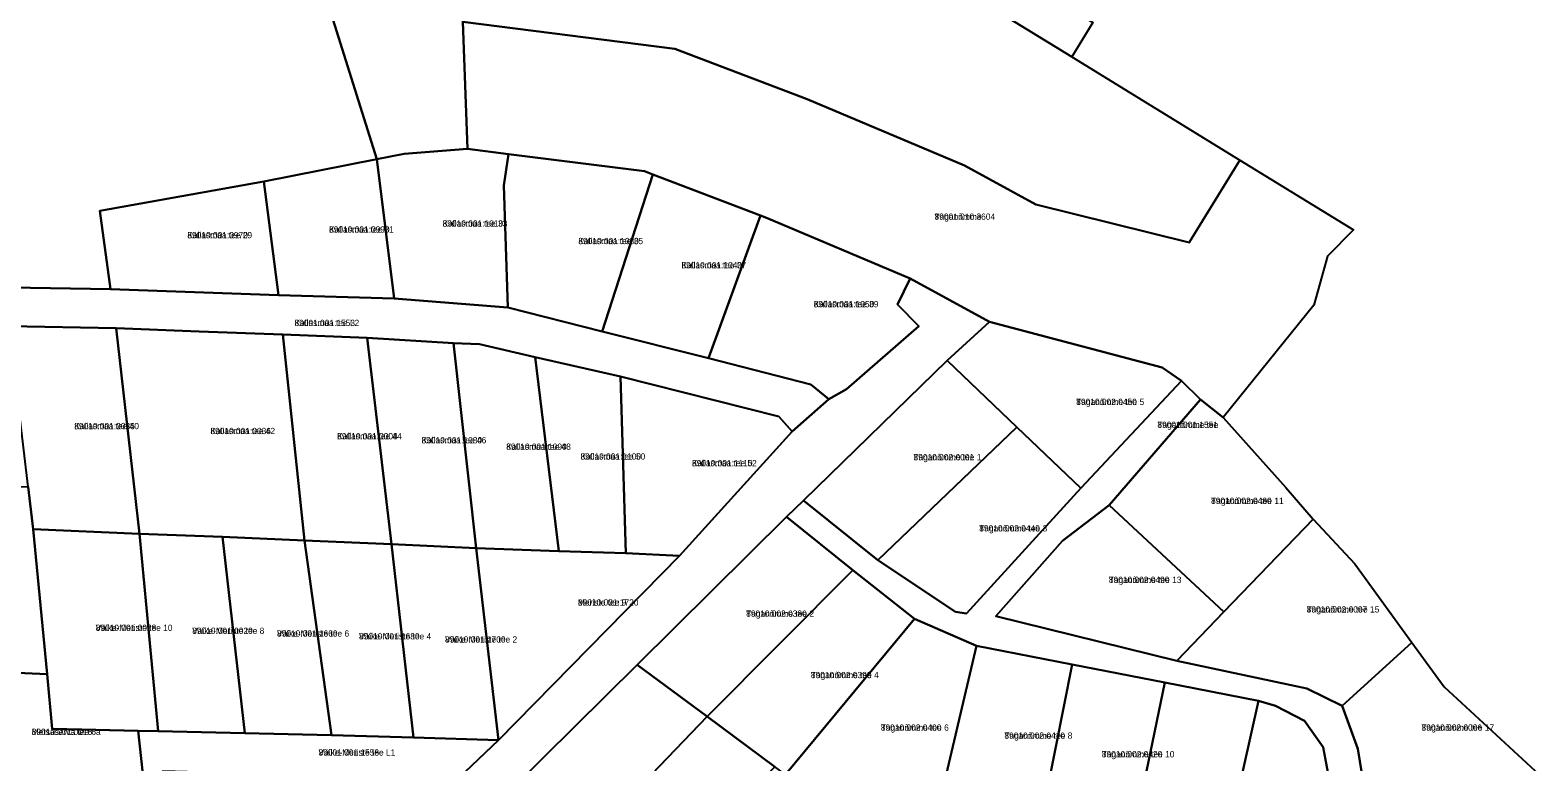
# Model space of a CAD drawing. Extents: x 526849 to 562296, y 6591741 to 6618546.
# Drawn here: x 554310.3 to 554671.4, y 6594193.2 to 6594368.5 of the extents above; entities that cross this region are included whole.
import ezdxf

# ---------------------------------------------------------------- set-up
doc = ezdxf.new("R2010")
doc.units = 0
for name, color, linetype in [('L_AADRESS', 7, 'Continuous'), ('PIIR', 7, 'Continuous'), ('TUNNUS', 7, 'Continuous')]:
    doc.layers.add(name, color=color, linetype=linetype)

msp = doc.modelspace()

# ---------------------------------------------------------------- linework, layer by layer
at = {"layer": 'PIIR'}
for points in [[(554049.07, 6594588.34), (554187.3, 6594577.01), (554142.16, 6594463.53), (554286.81, 6594430.65), (554294.86, 6594427.18), (554295.56, 6594417.13), (554326.06, 6594416.22), (554335.74, 6594428.53), (554338.1, 6594444.44), (554360.54, 6594442.08), (554393.31, 6594337.56), (554366.29, 6594332.23), (554326.99, 6594325.2), (554329.5, 6594306.39), (554305.59, 6594306.85), (554225.23, 6594322.81), (554036.66, 6594366.61)], [(554305.59, 6594306.85), (554329.5, 6594306.39), (554369.75, 6594304.99), (554397.46, 6594304.16), (554424.66, 6594301.99), (554447.31, 6594296.3), (554472.76, 6594289.86), (554497.3, 6594283.58), (554501.59, 6594280.09), (554492.83, 6594272.35), (554489.57, 6594275.93), (554451.7, 6594285.47), (554431.24, 6594290.14), (554417.89, 6594293.24), (554411.68, 6594293.51), (554390.97, 6594294.75), (554370.83, 6594295.54), (554350.75, 6594296.3), (554330.91, 6594297.04), (554305.24, 6594297.53)], [(554411.23, 6594187.68), (554422.5, 6594198.4), (554465.85, 6594242.5), (554492.83, 6594272.35), (554501.59, 6594280.09), (554505.83, 6594282.48), (554523.17, 6594297.53), (554518.04, 6594302.76), (554521.06, 6594309), (554540.09, 6594298.62), (554529.89, 6594289.33), (554495.51, 6594255.82), (554491.47, 6594251.85), (554455.65, 6594216.4), (554418.25, 6594179.39)], [(554626.73, 6594160.33), (554619.98, 6594196.69), (554615.53, 6594203.03), (554608.54, 6594206.57), (554604.47, 6594207.81), (554582.04, 6594212.17), (554559.86, 6594216.48), (554536.91, 6594220.94), (554522.13, 6594227.43), (554507.34, 6594239.07), (554491.47, 6594251.85), (554495.51, 6594255.82), (554513.32, 6594241.5), (554531.9, 6594229.09), (554534.57, 6594228.7), (554561.91, 6594258.7), (554586.03, 6594284.44), (554590.6, 6594280), (554568.68, 6594254.67), (554557.51, 6594246.16), (554541.54, 6594228.07), (554584.91, 6594217.38), (554616.09, 6594210.77), (554624.55, 6594206.56), (554628.29, 6594196.3), (554631.02, 6594179.48)]]:
    msp.add_lwpolyline(points, dxfattribs=at)
for points in [[(554220.53, 6594569.15), (554236.78, 6594565.3), (554439.73, 6594437.33), (554412, 6594426.5), (554413.94, 6594370.43), (554415.01, 6594340.05), (554399.87, 6594338.88), (554393.31, 6594337.56), (554360.54, 6594442.08), (554382.97, 6594439.71), (554400.23, 6594453.41), (554392.87, 6594457.11), (554332.13, 6594494.16), (554269.63, 6594532.29), (554204.27, 6594572.99)], [(554318.53, 6594513.75), (554391.09, 6594478.7), (554564.82, 6594370.34), (554559.78, 6594362.1), (554528.75, 6594381.2), (554439.73, 6594437.33)], [(554439.73, 6594437.33), (554528.75, 6594381.2), (554559.78, 6594362.1), (554600, 6594337.35), (554587.86, 6594317.61), (554551.17, 6594326.74), (554534.06, 6594336.06), (554496.36, 6594351.91), (554464.73, 6594363.97), (554413.94, 6594370.43), (554412, 6594426.5)], [(554413.94, 6594370.43), (554464.73, 6594363.97), (554496.36, 6594351.91), (554534.06, 6594336.06), (554551.17, 6594326.74), (554587.86, 6594317.61), (554600, 6594337.35), (554627.24, 6594320.6), (554621.04, 6594314.29), (554617.77, 6594302.58), (554596.03, 6594275.66), (554590.6, 6594280), (554586.03, 6594284.44), (554581.39, 6594287.66), (554540.09, 6594298.62), (554521.06, 6594309), (554486.63, 6594323.53), (554485.24, 6594324.08), (554459.4, 6594333.91), (554457.41, 6594334.66), (554424.85, 6594338.79), (554415.01, 6594340.05)], [(554423.76, 6594331.23), (554424.66, 6594301.99), (554397.46, 6594304.16), (554393.31, 6594337.56), (554399.87, 6594338.88), (554415.01, 6594340.05), (554424.85, 6594338.79)], [(554459.4, 6594333.91), (554447.31, 6594296.3), (554424.66, 6594301.99), (554423.76, 6594331.23), (554424.85, 6594338.79), (554457.41, 6594334.66)], [(554393.31, 6594337.56), (554397.46, 6594304.16), (554369.75, 6594304.99), (554366.29, 6594332.23)], [(554366.29, 6594332.23), (554369.75, 6594304.99), (554329.5, 6594306.39), (554326.99, 6594325.2)], [(554485.24, 6594324.08), (554472.76, 6594289.86), (554447.31, 6594296.3), (554459.4, 6594333.91)], [(554518.04, 6594302.76), (554523.17, 6594297.53), (554505.83, 6594282.48), (554501.59, 6594280.09), (554497.3, 6594283.58), (554472.76, 6594289.86), (554485.24, 6594324.08), (554486.63, 6594323.53), (554521.06, 6594309)], [(554305.24, 6594297.53), (554330.91, 6594297.04), (554336.45, 6594247.79), (554311.04, 6594248.95), (554309.82, 6594259.09)], [(554330.91, 6594297.04), (554350.75, 6594296.3), (554370.83, 6594295.54), (554376.01, 6594246.17), (554356.37, 6594247.09), (554336.45, 6594247.79)], [(554370.83, 6594295.54), (554390.97, 6594294.75), (554396.8, 6594245.31), (554376.01, 6594246.17)], [(554546.64, 6594273.32), (554529.89, 6594289.33), (554540.09, 6594298.62), (554581.39, 6594287.66), (554586.03, 6594284.44), (554561.91, 6594258.7)], [(554396.8, 6594245.31), (554390.97, 6594294.75), (554411.68, 6594293.51), (554417.1, 6594244.35)], [(554417.1, 6594244.35), (554411.68, 6594293.51), (554417.89, 6594293.24), (554431.24, 6594290.14), (554436.93, 6594243.68)], [(554436.93, 6594243.68), (554431.24, 6594290.14), (554451.7, 6594285.47), (554452.97, 6594243.17)], [(554529.89, 6594289.33), (554546.64, 6594273.32), (554513.32, 6594241.5), (554495.51, 6594255.82)], [(554452.97, 6594243.17), (554451.7, 6594285.47), (554489.57, 6594275.93), (554492.83, 6594272.35), (554465.85, 6594242.5)], [(554568.68, 6594254.67), (554590.6, 6594280), (554596.03, 6594275.66), (554611.02, 6594258.92), (554617.56, 6594251.34), (554596.17, 6594229.09)], [(554513.32, 6594241.5), (554546.64, 6594273.32), (554561.91, 6594258.7), (554534.57, 6594228.7), (554531.9, 6594229.09)], [(554282.31, 6594215.6), (554274.63, 6594260.46), (554309.82, 6594259.09), (554311.04, 6594248.95), (554314.34, 6594214.15)], [(554557.51, 6594246.16), (554568.68, 6594254.67), (554596.17, 6594229.09), (554584.91, 6594217.38), (554541.54, 6594228.07)], [(554311.04, 6594248.95), (554336.45, 6594247.79), (554340.94, 6594200.49), (554336.2, 6594200.59), (554322.63, 6594200.89), (554315.58, 6594201.04), (554314.34, 6594214.15)], [(554455.65, 6594216.4), (554491.47, 6594251.85), (554507.34, 6594239.07), (554472.4, 6594204)], [(554624.55, 6594206.56), (554616.09, 6594210.77), (554584.91, 6594217.38), (554596.17, 6594229.09), (554617.56, 6594251.34), (554627.54, 6594240.58), (554641.2, 6594221.8)], [(554336.45, 6594247.79), (554356.37, 6594247.09), (554361.74, 6594200.04), (554340.94, 6594200.49)], [(554376.01, 6594246.17), (554382.46, 6594199.55), (554361.74, 6594200.04), (554356.37, 6594247.09)], [(554396.8, 6594245.31), (554402.12, 6594199.02), (554382.46, 6594199.55), (554376.01, 6594246.17)], [(554417.1, 6594244.35), (554422.5, 6594198.4), (554402.12, 6594199.02), (554396.8, 6594245.31)], [(554452.97, 6594243.17), (554465.85, 6594242.5), (554422.5, 6594198.4), (554417.1, 6594244.35), (554436.93, 6594243.68)], [(554472.4, 6594204), (554507.34, 6594239.07), (554522.13, 6594227.43), (554491.16, 6594190.12), (554488.63, 6594192.01)], [(554491.16, 6594190.12), (554522.13, 6594227.43), (554536.91, 6594220.94), (554527.41, 6594180.54), (554520.69, 6594181.69), (554497.25, 6594188.38)], [(554527.41, 6594180.54), (554536.91, 6594220.94), (554559.86, 6594216.48), (554551.86, 6594176.24), (554544.93, 6594177.55)], [(554631.02, 6594179.48), (554628.29, 6594196.3), (554624.55, 6594206.56), (554641.2, 6594221.8), (554648.93, 6594211.15), (554670.76, 6594191.04), (554671.39, 6594187.62)], [(554418.25, 6594179.39), (554455.65, 6594216.4), (554472.4, 6594204), (554436.47, 6594166.48)], [(554551.86, 6594176.24), (554559.86, 6594216.48), (554582.04, 6594212.17), (554573.77, 6594172.01), (554567.21, 6594173.35)], [(554282.31, 6594215.6), (554314.34, 6594214.15), (554315.58, 6594201.04), (554336.2, 6594200.59), (554338.01, 6594183.63), (554287.78, 6594183.63)], [(554573.77, 6594172.01), (554582.04, 6594212.17), (554604.47, 6594207.81), (554595.48, 6594167.4), (554588.68, 6594168.94)], [(554608.54, 6594206.57), (554615.53, 6594203.03), (554619.98, 6594196.69), (554626.73, 6594160.33), (554610.53, 6594163.99), (554595.48, 6594167.4), (554604.47, 6594207.81)], [(554488.63, 6594192.01), (554453.73, 6594155.68), (554436.47, 6594166.48), (554472.4, 6594204)], [(554402.12, 6594199.02), (554422.5, 6594198.4), (554411.23, 6594187.68), (554374.17, 6594190.04), (554342.09, 6594190.95), (554344.95, 6594163.94), (554349.5, 6594123.33), (554345.18, 6594118.56), (554341.75, 6594148.51), (554340.87, 6594159.31), (554340.2, 6594163.84), (554339.05, 6594173.82), (554338.01, 6594183.63), (554336.2, 6594200.59), (554340.94, 6594200.49), (554361.74, 6594200.04), (554382.46, 6594199.55)]]:
    msp.add_lwpolyline(points, close=True, dxfattribs=at)

# ---------------------------------------------------------------- texts
at = {"layer": 'L_AADRESS'}
for s, p in [('Taganõmme', (554526.9, 6594323.04)), ('Kallasmaa tee 31', (554381.88, 6594319.97)), ('Kallasmaa tee 33', (554409.08, 6594321.41)), ('Kallasmaa tee 29', (554347.94, 6594318.61)), ('Kallasmaa tee 35', (554441.58, 6594317.2)), ('Kallasmaa tee 37', (554466.28, 6594311.4)), ('Kallasmaa tee 39', (554497.96, 6594302.08)), ('Kallasmaa tee L2', (554373.6, 6594297.58)), ('Taganõmme tee 5', (554560.83, 6594278.66)), ('Kallasmaa tee 40', (554320.85, 6594272.87)), ('Taganõmme tee', (554580.27, 6594273.18)), ('Kallasmaa tee 42', (554353.46, 6594271.69)), ('Kallasmaa tee 44', (554383.81, 6594270.44)), ('Kallasmaa tee 46', (554404.04, 6594269.47)), ('Kallasmaa tee 48', (554424.3, 6594267.93)), ('Kallasmaa tee 50', (554442.11, 6594265.59)), ('Taganõmme tee 1', (554521.86, 6594265.41)), ('Kallasmaa tee 52', (554468.81, 6594263.99)), ('Taganõmme tee 11', (554593.12, 6594254.96)), ('Taganõmme tee 3', (554537.61, 6594248.37)), ('Taganõmme tee 13', (554568.64, 6594236.03)), ('Meriste tee 9', (554441.48, 6594230.62)), ('Taganõmme tee 15', (554616.02, 6594228.95)), ('Taganõmme tee 2', (554481.77, 6594227.93)), ('Väike-Meriste tee 10', (554325.99, 6594224.54)), ('Väike-Meriste tee 8', (554349.1, 6594223.83)), ('Väike-Meriste tee 6', (554369.41, 6594223.17)), ('Väike-Meriste tee 4', (554389.06, 6594222.5)), ('Väike-Meriste tee 2', (554409.65, 6594221.75)), ('Taganõmme tee 4', (554497.27, 6594213.22)), ('Taganõmme tee 6', (554514.03, 6594200.63)), ('Taganõmme tee 17', (554643.52, 6594200.64)), ('Metsaserva tee 6a', (554310.67, 6594199.62)), ('Taganõmme tee 8', (554543.63, 6594198.7)), ('Väike-Meriste tee L1', (554379.35, 6594194.67)), ('Taganõmme tee 10', (554566.95, 6594194.25))]:
    msp.add_text(s, height=1.5, dxfattribs=at).set_placement(p)
at = {"layer": 'TUNNUS'}
for s, p in [('89001:010:3604', (554526.9, 6594323.04)), ('89010:001:0990', (554381.88, 6594319.97)), ('89010:001:1010', (554409.08, 6594321.41)), ('89010:001:0970', (554347.94, 6594318.61)), ('89010:001:1030', (554441.58, 6594317.2)), ('89010:001:1040', (554466.28, 6594311.4)), ('89010:001:1050', (554497.96, 6594302.08)), ('89001:001:1553', (554373.6, 6594297.58)), ('89010:002:0450', (554560.83, 6594278.66)), ('89010:001:0035', (554320.85, 6594272.87)), ('89001:001:1551', (554580.27, 6594273.18)), ('89010:001:0036', (554353.46, 6594271.69)), ('89010:001:0008', (554383.81, 6594270.44)), ('89010:001:1080', (554404.04, 6594269.47)), ('89010:001:1090', (554424.3, 6594267.93)), ('89010:001:1100', (554442.11, 6594265.59)), ('89010:002:0001', (554521.86, 6594265.41)), ('89010:001:1110', (554468.81, 6594263.99)), ('89010:002:0480', (554593.12, 6594254.96)), ('89010:002:0440', (554537.61, 6594248.37)), ('89010:002:0490', (554568.64, 6594236.03)), ('89010:001:1720', (554441.48, 6594230.62)), ('89010:002:0007', (554616.02, 6594228.95)), ('89010:002:0380', (554481.77, 6594227.93)), ('89010:001:0028', (554325.99, 6594224.54)), ('89010:001:0029', (554349.1, 6594223.83)), ('89010:001:1660', (554369.41, 6594223.17)), ('89010:001:1680', (554389.06, 6594222.5)), ('89010:001:1700', (554409.65, 6594221.75)), ('89010:002:0390', (554497.27, 6594213.22)), ('89010:002:0400', (554514.03, 6594200.63)), ('89010:002:0006', (554643.52, 6594200.64)), ('89010:001:0018', (554310.67, 6594199.62)), ('89010:002:0410', (554543.63, 6594198.7)), ('89001:001:1558', (554379.35, 6594194.67)), ('89010:002:0420', (554566.95, 6594194.25))]:
    msp.add_text(s, height=1.5, dxfattribs=at).set_placement(p)

doc.saveas('drawing.dxf')
